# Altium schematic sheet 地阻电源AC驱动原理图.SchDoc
size A3
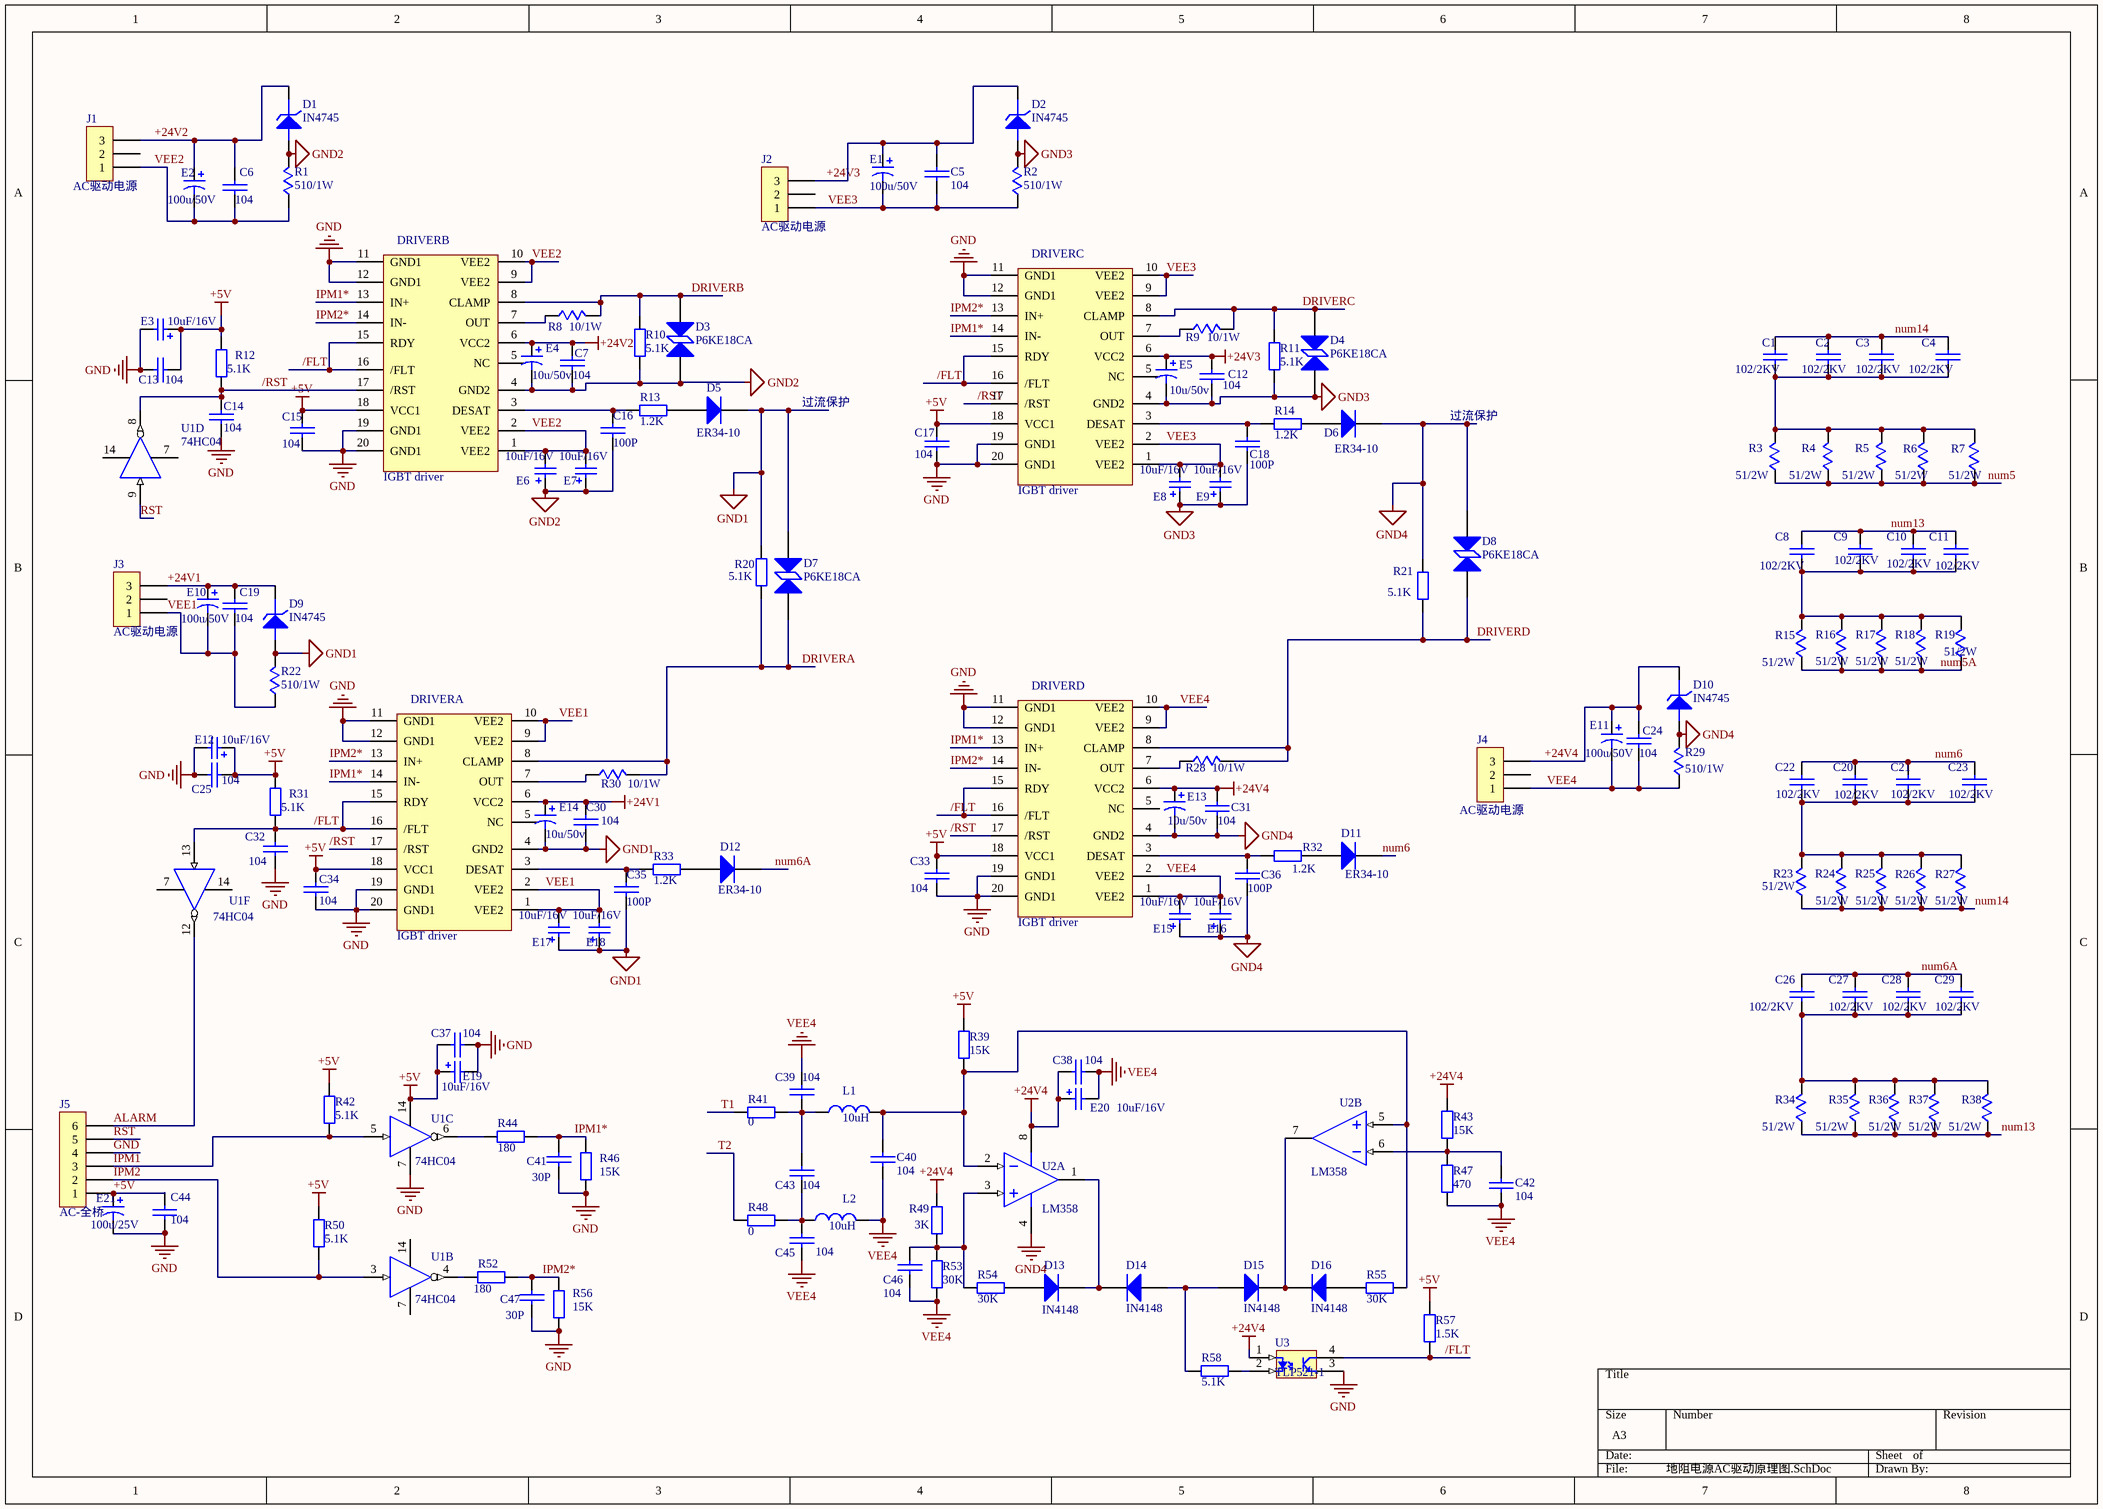
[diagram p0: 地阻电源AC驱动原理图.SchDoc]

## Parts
C1  102/2KV  [CP-7.5]
C2  102/2KV  [CP-7.5]
C3  102/2KV  [CP-7.5]
C4  102/2KV  [CP-7.5]
C5  104  [0805C]
C6  104  [0805C]
C7  104  [0805C]
C8  102/2KV  [CP-7.5]
C9  102/2KV  [CP-7.5]
C10  102/2KV  [CP-7.5]
C11  102/2KV  [CP-7.5]
C12  104  [0805C]
C13  104  [0805C]
C14  104  [0805C]
C15  104  [0805C]
C16  100P  [0805C]
C17  104  [0805C]
C18  100P  [0805C]
C19  104  [0805C]
C20  102/2KV  [CP-7.5]
C21  102/2KV  [CP-7.5]
C22  102/2KV  [CP-7.5]
C23  102/2KV  [CP-7.5]
C24  104  [0805C]
C25  104  [0805C]
C26  102/2KV  [CP-7.5]
C27  102/2KV  [CP-7.5]
C28  102/2KV  [CP-7.5]
C29  102/2KV  [CP-7.5]
C30  104  [0805C]
C31  104  [0805C]
C32  104  [0805C]
C33  104  [0805C]
C34  104  [0805C]
C35  100P  [0805C]
C36  100P  [0805C]
C37  104  [0805C]
C38  104  [0805C]
C39  104  [0805C]
C40  104  [0805C]
C41  30P  [0805C]
C42  104  [0805C]
C43  104  [0805C]
C44  104  [0805C]
C45  104  [0805C]
C46  104  [0805C]
C47  30P  [0805C]
D1  IN4745  [DIODE0.3-0.1]
D2  IN4745  [DIODE0.3-0.1]
D3  P6KE18CA  [DIODE0.3-AC]
D4  P6KE18CA  [DIODE0.3-AC]
D5  ER34-10  [DIODE0.2]
D6  ER34-10  [DIODE0.2]
D7  P6KE18CA  [DIODE0.3-AC]
D8  P6KE18CA  [DIODE0.3-AC]
D9  IN4745  [DIODE0.3-0.1]
D10  IN4745  [DIODE0.3-0.1]
D11  ER34-10  [DIODE0.2]
D12  ER34-10  [DIODE0.2]
D13  IN4148  [DIODE-SMD0.15]
D14  IN4148  [DIODE-SMD0.15]
D15  IN4148  [DIODE-SMD0.15]
D16  IN4148  [DIODE-SMD0.15]
DRIVERA  IGBT driver  [SOP20-7.6-1.27]
DRIVERB  IGBT driver  [SOP20-7.6-1.27]
DRIVERC  IGBT driver  [SOP20-7.6-1.27]
DRIVERD  IGBT driver  [SOP20-7.6-1.27]
E1  100u/50V  [E2.5-7]
E2  100u/50V  [E2.5-7]
E3  10uF/16V  [1210E]
E4  10u/50v  [E0.1/R0.1]
E5  10u/50v  [E0.1/R0.1]
E6  10uF/16V  [1210E]
E7  10uF/16V  [1210E]
E8  10uF/16V  [1210E]
E9  10uF/16V  [1210E]
E10  100u/50V  [E2.5-7]
E11  100u/50V  [E2.5-7]
E12  10uF/16V  [1210E]
E13  10u/50v  [E0.1/R0.1]
E14  10u/50v  [E0.1/R0.1]
E15  10uF/16V  [1210E]
E16  10uF/16V  [1210E]
E17  10uF/16V  [1210E]
E18  10uF/16V  [1210E]
E19  10uF/16V  [1210E]
E20  10uF/16V  [1210E]
E21  100u/25V  [E0.1/R0.12]
J1  AC驱动电源  [CON03]
J2  AC驱动电源  [CON03]
J3  AC驱动电源  [CON03]
J4  AC驱动电源  [CON03]
J5  AC-全桥  [CON06]
L1  10uH  [L10UH-SMD]
L2  10uH  [L10UH-SMD]
R1  510/1W  [RES0.1-1W-STAND]
R2  510/1W  [RES0.1-1W-STAND]
R3  51/2W  [RES0.8-2W]
R4  51/2W  [RES0.8-2W]
R5  51/2W  [RES0.8-2W]
R6  51/2W  [RES0.8-2W]
R7  51/2W  [RES0.8-2W]
R8  10/1W  [RES0.1-1W-STAND]
R9  10/1W  [RES0.1-1W-STAND]
R10  5.1K  [0805R]
R11  5.1K  [0805R]
R12  5.1K  [0805R]
R13  1.2K  [0805R]
R14  1.2K  [0805R]
R15  51/2W  [RES0.8-2W]
R16  51/2W  [RES0.8-2W]
R17  51/2W  [RES0.8-2W]
R18  51/2W  [RES0.8-2W]
R19  51/2W  [RES0.8-2W]
R20  5.1K  [0805R]
R21  5.1K  [0805R]
R22  510/1W  [RES0.1-1W-STAND]
R23  51/2W  [RES0.8-2W]
R24  51/2W  [RES0.8-2W]
R25  51/2W  [RES0.8-2W]
R26  51/2W  [RES0.8-2W]
R27  51/2W  [RES0.8-2W]
R28  10/1W  [RES0.1-1W-STAND]
R29  510/1W  [RES0.1-1W-STAND]
R30  10/1W  [RES0.1-1W-STAND]
R31  5.1K  [0805R]
R32  1.2K  [0805R]
R33  1.2K  [0805R]
R34  51/2W  [RES0.8-2W]
R35  51/2W  [RES0.8-2W]
R36  51/2W  [RES0.8-2W]
R37  51/2W  [RES0.8-2W]
R38  51/2W  [RES0.8-2W]
R39  15K  [0805R]
R41  0  [0805R]
R42  5.1K  [0805R]
R43  15K  [0805R]
R44  180  [0805R]
R46  15K  [0805R]
R47  470  [0805R]
R48  0  [0805R]
R49  3K  [0805R]
R50  5.1K  [0805R]
R52  180  [0805R]
R53  30K  [0805R]
R54  30K  [0805R]
R55  30K  [0805R]
R56  15K  [0805R]
R57  1.5K  [0805R]
R58  5.1K  [0805R]
U1  74HC04  [SOP14]  (parts B,C,D,F of 6)
U2  LM358  [SOP08]  (parts A,B of 2)
U3  TLP521-1  [DIP04]

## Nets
+5V: C13.1 C15.1 C17.1 C25.1 C33.1 C34.1 C37.1 C44.1 DRIVERA.18(VCC1) DRIVERB.18(VCC1) DRIVERC.18(VCC1) DRIVERD.18(VCC1) E3.1 E12.1 E19.1 E21.1 J5.1 R12.2 R31.2 R39.1 R42.2 R50.2 R57.1 U1.14
+24V1: C19.2 C30.1 D9.2(K) DRIVERA.6(VCC2) E10.1 E14.1 J3.3
+24V2: C6.2 C7.1 D1.2(K) DRIVERB.6(VCC2) E2.1 E4.1 J1.3
+24V3: C5.2 C12.1 D2.2(K) DRIVERC.6(VCC2) E1.1 E5.1 J2.3
+24V4: C24.1 C31.1 C38.1 D10.2(K) DRIVERD.6(VCC2) E11.1 E13.1 E20.1 J4.3 R43.1 R49.2 U2.8(V+) U3.1
GND: C13.2 C14.2 C15.2 C17.2 C25.2 C32.2 C33.2 C34.2 C37.2 C41.2 C44.2 C47.2 DRIVERA.11(GND1) DRIVERA.12(GND1) DRIVERA.19(GND1) DRIVERA.20(GND1) DRIVERB.11(GND1) DRIVERB.12(GND1) DRIVERB.19(GND1) DRIVERB.20(GND1) DRIVERC.11(GND1) DRIVERC.12(GND1) DRIVERC.19(GND1) DRIVERC.20(GND1) DRIVERD.11(GND1) DRIVERD.12(GND1) DRIVERD.19(GND1) DRIVERD.20(GND1) E3.2 E12.2 E19.2 E21.2 J5.4 R46.1 R56.1 U1.7 U3.3
GND1: C30.2 C35.2 D5.2 D7.1(A) D9.1(A) DRIVERA.4(GND2) E14.2 E17.1 E18.1 R20.1 R22.2
GND2: C7.2 C16.2 D1.1(A) D3.1(A) DRIVERB.4(GND2) E4.2 E6.1 E7.1 R1.2 R10.1
GND3: C12.2 C18.2 D2.1(A) D4.1(A) DRIVERC.4(GND2) E5.2 E8.1 E9.1 R2.2 R11.1
GND4: C31.2 C36.2 D6.2 D8.1(A) D10.1(A) DRIVERD.4(GND2) E13.2 E15.1 E16.1 R21.1 R29.2 U2.4(GND)
VEE4: C24.2 C38.2 C39.1 C40.2 C42.2 C45.2 C46.2 DRIVERD.1(VEE2) DRIVERD.2(VEE2) DRIVERD.9(VEE2) DRIVERD.10(VEE2) E11.2 E15.2 E16.2 E20.2 J4.1 L2.2 R29.1 R47.2 R53.1
/FLT: C32.1 DRIVERA.15(RDY) DRIVERA.16(/FLT) DRIVERB.15(RDY) DRIVERB.16(/FLT) DRIVERC.15(RDY) DRIVERC.16(/FLT) DRIVERD.15(RDY) DRIVERD.16(/FLT) R31.1 R57.2 U1.13(A) U3.4
/RST: C14.1 DRIVERA.17(/RST) DRIVERB.17(/RST) DRIVERC.17(/RST) DRIVERD.17(/RST) R12.1 U1.8(Y)
ALARM: J5.6 U1.12(Y)
DRIVERA: D7.2(K) DRIVERA.8(CLAMP) R20.2 R30.2
DRIVERB: D3.2(K) DRIVERB.8(CLAMP) R8.2 R10.2
DRIVERC: D4.2(K) DRIVERC.8(CLAMP) R9.2 R11.2
DRIVERD: D8.2(K) DRIVERD.8(CLAMP) R21.2 R28.2
IPM1: J5.3 R42.1 U1.5(A)
IPM1*: C41.1 DRIVERA.14(IN-) DRIVERB.13(IN+) DRIVERC.14(IN-) DRIVERD.13(IN+) R44.2 R46.2
IPM2: J5.2 R50.1 U1.3(A)
IPM2*: C47.1 DRIVERA.13(IN+) DRIVERB.14(IN-) DRIVERC.13(IN+) DRIVERD.14(IN-) R52.2 R56.2
num5: R3.1 R4.1 R5.1 R6.1 R7.1
num5A: R15.1 R16.1 R17.1 R18.1 R19.1
num6: C20.1 C21.1 C22.1 C23.1 D11.2
num6A: C26.1 C27.1 C28.1 C29.1 D12.2
num13: C8.1 C9.1 C10.1 C11.1 R34.1 R35.1 R36.1 R37.1 R38.1
num14: C1.1 C2.1 C3.1 C4.1 R23.1 R24.1 R25.1 R26.1 R27.1
RST: J5.5 U1.9(A)
T1: R41.1
T2: R48.1
VEE1: C19.1 DRIVERA.1(VEE2) DRIVERA.2(VEE2) DRIVERA.9(VEE2) DRIVERA.10(VEE2) E10.2 E17.2 E18.2 J3.1 R22.1
VEE2: C6.1 DRIVERB.1(VEE2) DRIVERB.2(VEE2) DRIVERB.9(VEE2) DRIVERB.10(VEE2) E2.2 E6.2 E7.2 J1.1 R1.1
VEE3: C5.1 DRIVERC.1(VEE2) DRIVERC.2(VEE2) DRIVERC.9(VEE2) DRIVERC.10(VEE2) E1.2 E8.2 E9.2 J2.1 R2.1
NetC1_2: C1.2 C2.2 C3.2 C4.2 R3.2 R4.2 R5.2 R6.2 R7.2
NetC8_2: C8.2 C9.2 C10.2 C11.2 R15.2 R16.2 R17.2 R18.2 R19.2
NetC16_1: C16.1 DRIVERB.3(DESAT) R13.2
NetC18_1: C18.1 DRIVERC.3(DESAT) R14.2
NetC20_2: C20.2 C21.2 C22.2 C23.2 R23.2 R24.2 R25.2 R26.2 R27.2
NetC26_2: C26.2 C27.2 C28.2 C29.2 R34.2 R35.2 R36.2 R37.2 R38.2
NetC35_1: C35.1 DRIVERA.3(DESAT) R33.2
NetC36_1: C36.1 DRIVERD.3(DESAT) R32.2
NetC39_2: C39.2 C43.1 L1.1 R41.2
NetC40_1: C40.1 L1.2 R39.2 R55.1 U2.2(IN-) U2.5(IN+)
NetC42_1: C42.1 R43.2 R47.1 U2.6(IN-)
NetC43_2: C43.2 C45.1 L2.1 R48.2
NetC46_1: C46.1 R49.1 R53.2 R54.2 U2.3(IN+)
NetD5_1: D5.1 R13.1
NetD6_1: D6.1 R14.1
NetD11_1: D11.1 R32.1
NetD12_1: D12.1 R33.1
NetD13_1: D13.1 R54.1
NetD13_2: D13.2 D14.2 U2.1(OUT)
NetD14_1: D14.1 D15.1 R58.1
NetD15_2: D15.2 D16.2 U2.7(OUT)
NetD16_1: D16.1 R55.2
NetDRIVERA_7: DRIVERA.7(OUT) R30.1
NetDRIVERB_7: DRIVERB.7(OUT) R8.1
NetDRIVERC_7: DRIVERC.7(OUT) R9.1
NetDRIVERD_7: DRIVERD.7(OUT) R28.1
NetR44_1: R44.1 U1.6(Y)
NetR52_1: R52.1 U1.4(Y)
NetR58_2: R58.2 U3.2

Not connected (* = marked no-connect by the designer): DRIVERA 5(NC); DRIVERB 5(NC); DRIVERC 5(NC); DRIVERD 5(NC); J1 2; J2 2; J3 2; J4 2

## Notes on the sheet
- 过流保护

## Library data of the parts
C1-C4 C8-C11 C20-C23 C26-C29 = Cap2: 高压瓷片电容
C5-C7 C12-C19 C24 C25 C30-C47 = Cap: 贴片电容
D1 D2 D9 D10 = Diode5: 稳压管
D3 D4 D7 D8 = D TVS2: 双向TVS管
D5 D6 D11-D16 = Diode1: 二极管
DRIVERA = IGBT driver: 单个IGBT驱动
E1 E2 E4 E5 E10 E11 E13 E14 E21 = Cap Pol: 电解电容
E3 E6-E9 E12 E15-E20 = Cap Pol3: 贴片电解电容; Value: 4.7uF/25V
J1-J4 = CON3: 接插件，3针
J5 = CON6: 接插件，6针
L1 L2 = Inductor1: 贴片电感; Code_IEC: 1005; Value: 10mH
R1-R9 R15-R19 R22-R30 R34-R38 = RES1: 金属膜电阻
R10-R14 R20 R21 R31-R33 R39 R41-R44 R46-R50 R52-R58 = RES2: 贴片电阻; Value: 1K
U1 = 74HC04: 6通道反相器; PackageDocument: 1991
U2 = LM358: 双运放
U3 = OPTO: 光耦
